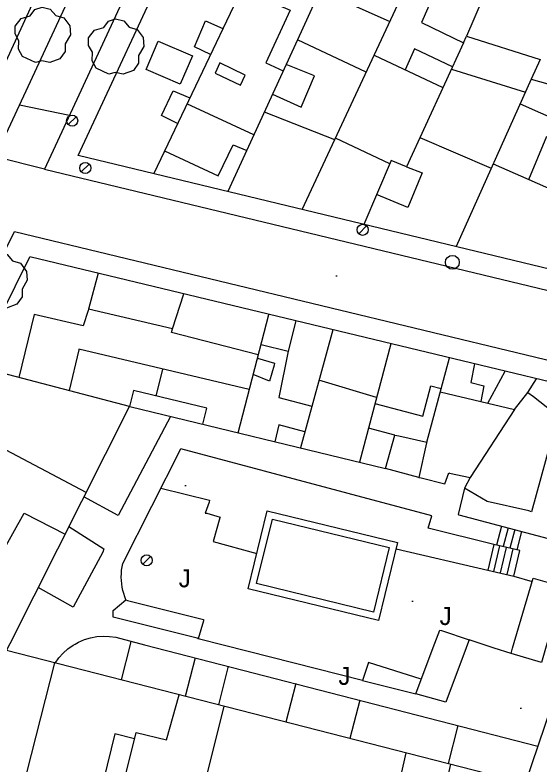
# Model space of a CAD drawing. Extents: x 431390 to 432653, y 4586754 to 4589600.
# Drawn here: x 432007.4 to 432045.3, y 4587636.5 to 4587690.5 of the extents above; entities that cross this region are included whole.
import ezdxf

# ---------------------------------------------------------------- set-up
doc = ezdxf.new("R2010")
doc.units = 0
for name, color, linetype in [('COM_17LS_LN', 7, 'Continuous'), ('COM_51_LN', 7, 'Continuous'), ('CON_01_LN', 7, 'Continuous'), ('CON_01FI_LN', 7, 'Continuous'), ('CON_03_LN', 7, 'Continuous'), ('CON_04_LN', 7, 'Continuous'), ('CON_07_LN', 7, 'Continuous'), ('CON_14LS_LN', 7, 'Continuous'), ('CON_15_LN', 7, 'Continuous'), ('CON_16_LN', 7, 'Continuous'), ('CON_23_LN', 7, 'Continuous'), ('CON_29_LN', 7, 'Continuous'), ('ENE_05_PT', 7, 'Continuous'), ('ENE_06_PT', 7, 'Continuous'), ('HID_11EX_LN', 7, 'Continuous'), ('HID_11IN_LN', 7, 'Continuous'), ('ORO_03_PT', 7, 'Continuous'), ('TOP_15JA_TX', 7, 'Continuous'), ('VEG_03_PT', 7, 'Continuous'), ('VEG_06_LN', 7, 'Continuous')]:
    doc.layers.add(name, color=color, linetype=linetype)

msp = doc.modelspace()

# ---------------------------------------------------------------- linework, layer by layer
at = {"layer": 'COM_17LS_LN'}
for points in [[(432006.024, 4587680.292), (432041.411, 4587756.509), (432044.673, 4587755.098), (432041.441, 4587748.129), (432031.405, 4587726.494), (432019.334, 4587700.469), (432009.569, 4587679.418), (432092.063, 4587659.53)], [(431996.705, 4587653.49), (432007.414, 4587674.901), (432066.476, 4587660.674)]]:
    msp.add_lwpolyline(points, dxfattribs=at)
at = {"layer": 'COM_51_LN'}
for points in [[(432007.767, 4587684.047), (432011.367, 4587683.294)], [(432009.569, 4587679.418), (432006.024, 4587680.292)]]:
    msp.add_lwpolyline(points, dxfattribs=at)
at = {"layer": 'CON_01_LN'}
for points in [[(432028.804, 4587732.074), (432027.658, 4587732.613), (432004.401, 4587682.062), (431964.751, 4587691.684)], [(432069.351, 4587666.555), (432012.008, 4587680.398), (432019.086, 4587695.657)], [(432149.679, 4587598.561), (432142.834, 4587600.154), (432120.838, 4587605.458), (432120.688, 4587605.494), (432084.332, 4587614.171), (432084.249, 4587614.151), (432049.937, 4587622.578), (431990.859, 4587637.415), (431994.764, 4587645.305), (432008.507, 4587673.078)], [(432080.515, 4587655.754), (432008.507, 4587673.078)]]:
    msp.add_lwpolyline(points, dxfattribs=at)
at = {"layer": 'CON_01FI_LN'}
for points in [[(432037.686, 4587692.072), (432036.767, 4587689.999), (432039.8, 4587688.515), (432040.023, 4587689.014), (432045.332, 4587687.328), (432044.693, 4587685.898), (432048.742, 4587684.772), (432051.08, 4587689.672), (432055.373, 4587687.519), (432063.231, 4587702.643)], [(432047.563, 4587644.797), (432044.268, 4587635.081), (432006.82, 4587644.663), (432007.084, 4587645.187), (432015.694, 4587662.285), (432015.737, 4587662.272), (432034.19, 4587657.797), (432034.86, 4587660.208), (432035.137, 4587660.172), (432037.16, 4587659.697), (432037.143, 4587659.656), (432036.593, 4587657.168), (432036.755, 4587657.127), (432038.472, 4587656.7), (432038.755, 4587657.502), (432038.809, 4587657.469), (432040.297, 4587657.161), (432039.882, 4587656.377), (432039.414, 4587654.497), (432039.468, 4587654.474), (432049.901, 4587651.69), (432047.563, 4587644.797)]]:
    msp.add_lwpolyline(points, dxfattribs=at)
at = {"layer": 'CON_03_LN'}
for points in [[(432026.951, 4587699.037), (432017.456, 4587679.083)], [(432031.928, 4587697.709), (432027.825, 4587688.744)], [(432028.171, 4587676.496), (432035.4, 4587692.026)], [(432027.825, 4587688.744), (432027.011, 4587686.967)], [(432039.8, 4587688.515), (432035.704, 4587679.584), (432034.583, 4587680.032), (432032.626, 4587675.421)], [(432027.011, 4587686.967), (432022.811, 4587677.79)], [(432044.693, 4587685.898), (432039.278, 4587673.815)], [(432023.536, 4587660.381), (432025.763, 4587668.927)], [(432030.382, 4587667.815), (432028.037, 4587659.289)], [(432034.552, 4587666.812), (432032.308, 4587658.253)], [(432037.16, 4587659.697), (432038.792, 4587665.792)], [(432015.694, 4587662.285), (432004.605, 4587665.192)], [(432044.454, 4587663.281), (432045.084, 4587664.278)], [(432043.499, 4587662.06), (432044.454, 4587663.281)], [(432043.499, 4587662.06), (432040.297, 4587657.161)], [(432010.29, 4587643.775), (432007.611, 4587633.208)]]:
    msp.add_lwpolyline(points, dxfattribs=at)
at = {"layer": 'CON_04_LN'}
for points in [[(432023.785, 4587692.384), (432027.29, 4587690.869), (432025.533, 4587687.079), (432026.794, 4587686.492)], [(432029.462, 4587692.321), (432034.488, 4587690.066)], [(432021.547, 4587687.681), (432020.394, 4587688.229), (432021.179, 4587690.103), (432022.445, 4587689.567)], [(432017.78, 4587688.645), (432020.246, 4587687.592), (432019.372, 4587685.545), (432016.905, 4587686.598), (432017.78, 4587688.645)], [(432032.788, 4587686.414), (432027.825, 4587688.744)], [(432039.009, 4587686.791), (432036.283, 4587688.1), (432035.586, 4587686.578)], [(432033.352, 4587687.626), (432038.323, 4587685.295)], [(432024.063, 4587686.196), (432022.226, 4587687.072), (432021.877, 4587686.341), (432023.714, 4587685.464), (432024.063, 4587686.196)], [(432026.033, 4587684.83), (432028.093, 4587683.874), (432029.057, 4587686.15), (432027.011, 4587686.967)], [(432038.932, 4587686.622), (432044.277, 4587684.969)], [(432019.18, 4587682.705), (432018.009, 4587683.271), (432018.864, 4587685.07), (432020.064, 4587684.563)], [(432043.898, 4587684.124), (432048.088, 4587682.264), (432049.392, 4587685.166), (432053.673, 4587684.023)], [(432024.68, 4587681.873), (432019.854, 4587684.123)], [(432044.533, 4587678.666), (432045.829, 4587681.781), (432048.52, 4587680.597), (432047.155, 4587677.517)], [(432018.242, 4587680.734), (432022.116, 4587678.933), (432023.182, 4587681.163), (432024.163, 4587680.745)], [(432035.704, 4587679.584), (432036.819, 4587679.14), (432035.79, 4587676.639), (432033.541, 4587677.578)], [(432044.533, 4587678.666), (432047.155, 4587677.517)], [(432013.441, 4587671.891), (432012.744, 4587669.315)], [(432018.811, 4587667.875), (432019.629, 4587670.402)], [(432025, 4587665.998), (432018.747, 4587667.628), (432018.811, 4587667.875), (432012.744, 4587669.315), (432012.713, 4587669.22), (432012.363, 4587668.104), (432008.833, 4587668.913), (432007.72, 4587664.375)], [(432027.715, 4587668.457), (432027.149, 4587666.272), (432026.489, 4587662.934), (432028.865, 4587662.299)], [(432024.349, 4587663.499), (432012.056, 4587666.427), (432012.057, 4587666.362), (432011.346, 4587663.425)], [(432025.199, 4587666.761), (432027.149, 4587666.272)], [(432024.94, 4587665.767), (432026.162, 4587665.415), (432026.137, 4587665.267), (432025.797, 4587664.103), (432024.631, 4587664.584)], [(432040.594, 4587665.358), (432040.326, 4587664.022), (432041.286, 4587663.772), (432041.059, 4587662.638)], [(432017.621, 4587663.037), (432018.107, 4587664.986)], [(432041.571, 4587662.517), (432042.804, 4587664.827)], [(432033.42, 4587662.494), (432036.876, 4587661.588), (432037.45, 4587663.778), (432038.2, 4587663.581)], [(432021.005, 4587660.994), (432021.285, 4587662.149), (432015.989, 4587663.432), (432015.694, 4587662.285)], [(432038.133, 4587663.331), (432043.499, 4587662.06)], [(432044.454, 4587663.281), (432044.858, 4587662.991), (432046.225, 4587661.91), (432046.324, 4587661.657), (432046.467, 4587661.177), (432046.463, 4587661.068), (432044.713, 4587654.69), (432044.513, 4587654.761), (432041.515, 4587655.419), (432039.882, 4587656.377)], [(432028.355, 4587660.446), (432026.49, 4587660.959), (432026.191, 4587659.737)], [(432034.86, 4587660.208), (432032.951, 4587660.707)], [(432012.571, 4587656.084), (432005.955, 4587659.561), (432002.96, 4587653.376), (432003.125, 4587653.286), (432006.464, 4587651.651), (432008.109, 4587654.589), (432011.052, 4587653.067)], [(432022.51, 4587640.648), (432020.707, 4587633.426), (432015.203, 4587634.799), (432016.192, 4587638.765), (432018.382, 4587638.218), (432019.282, 4587641.474)], [(432016.077, 4587638.303), (432014.655, 4587638.658), (432013.82, 4587635.319), (432015.244, 4587634.963)], [(432038.859, 4587636.465), (432037.219, 4587629.268), (432031.639, 4587630.539), (432032.567, 4587634.615), (432034.94, 4587634.074), (432035.67, 4587637.281)]]:
    msp.add_lwpolyline(points, dxfattribs=at)
at = {"layer": 'CON_07_LN'}
for points in [[(432043.239, 4587644.448), (432043.353, 4587644.838), (432044.833, 4587649.904), (432047.021, 4587649.264), (432045.721, 4587644.815), (432045.427, 4587643.808), (432043.239, 4587644.448)], [(432015.452, 4587648.323), (432015.559, 4587648.284), (432021.052, 4587646.902), (432021.037, 4587646.826), (432020.652, 4587645.525), (432020.583, 4587645.565), (432014.528, 4587647.075), (432014.519, 4587647.181), (432014.516, 4587647.568), (432015.452, 4587648.323)], [(432036.364, 4587641.555), (432037.63, 4587644.893), (432038.104, 4587646.141), (432038.209, 4587646.127), (432040.216, 4587645.444), (432040.175, 4587645.317), (432040.008, 4587644.87), (432038.538, 4587640.935), (432036.364, 4587641.555)], [(432036.764, 4587642.61), (432032.944, 4587643.802), (432032.524, 4587642.511), (432036.364, 4587641.555)]]:
    msp.add_lwpolyline(points, dxfattribs=at)
at = {"layer": 'CON_14LS_LN'}
for points in [[(432041.999, 4587652.33), (432037.267, 4587653.498), (432037.532, 4587654.386), (432019.402, 4587659.236)], [(432043.447, 4587650.039), (432044.76, 4587649.655)]]:
    msp.add_lwpolyline(points, dxfattribs=at)
at = {"layer": 'CON_15_LN'}
msp.add_lwpolyline([(432041.76, 4587693.043), (432040.023, 4587689.014)], dxfattribs=at)
at = {"layer": 'CON_16_LN'}
for points in [[(432018.655, 4587661.564), (432014.9, 4587654.419), (432012.408, 4587655.759)], [(432015.452, 4587648.323), (432015.364, 4587648.549), (432015.289, 4587648.78), (432015.227, 4587649.014), (432015.178, 4587649.252), (432015.143, 4587649.492), (432015.121, 4587649.734), (432015.113, 4587649.977), (432015.118, 4587650.219), (432015.136, 4587650.461), (432015.168, 4587650.702), (432015.214, 4587650.941), (432019.402, 4587659.236)], [(432036.593, 4587657.168), (432034.19, 4587657.797)], [(432011.331, 4587653.622), (432013.855, 4587652.002), (432013.772, 4587651.777), (432011.635, 4587647.789), (432009.114, 4587649.219)], [(432010.348, 4587643.76), (432010.614, 4587644.133), (432010.92, 4587644.476), (432011.261, 4587644.783), (432011.634, 4587645.05), (432011.796, 4587645.141), (432012.034, 4587645.276), (432012.456, 4587645.456), (432012.895, 4587645.59), (432013.347, 4587645.674), (432013.804, 4587645.709), (432014.263, 4587645.694), (432014.718, 4587645.629), (432016.796, 4587645.093), (432045.182, 4587637.775)], [(432015.814, 4587645.346), (432015.752, 4587645.103), (432015.097, 4587642.545)], [(432032.524, 4587642.511), (432022.571, 4587645.038), (432020.652, 4587645.525)], [(432020.449, 4587644.151), (432019.734, 4587641.359)], [(432022.837, 4587643.536), (432022.123, 4587640.747)], [(432027.697, 4587642.283), (432026.985, 4587639.503)], [(432032.324, 4587641.09), (432031.615, 4587638.319)], [(432039.398, 4587639.266), (432038.692, 4587636.508)]]:
    msp.add_lwpolyline(points, dxfattribs=at)
at = {"layer": 'CON_23_LN'}
for points in [[(432042.554, 4587653.65), (432042.19, 4587652.285)], [(432043.036, 4587653.522), (432042.676, 4587652.171)], [(432043.518, 4587653.393), (432043.162, 4587652.057)], [(432044, 4587653.265), (432043.648, 4587651.943)], [(432041.999, 4587652.33), (432041.565, 4587650.481)], [(432041.989, 4587650.381), (432042.423, 4587652.23)], [(432043.447, 4587650.039), (432043.881, 4587651.888), (432041.999, 4587652.33)], [(432042.475, 4587650.267), (432042.909, 4587652.116)], [(432042.961, 4587650.153), (432043.395, 4587652.002)], [(432041.565, 4587650.481), (432043.447, 4587650.039)]]:
    msp.add_lwpolyline(points, dxfattribs=at)
at = {"layer": 'CON_29_LN'}
for points in [[(432030.515, 4587681.532), (432025.436, 4587683.526)], [(432034.486, 4587679.803), (432030.565, 4587681.639)], [(432036.668, 4587681.687), (432041.814, 4587679.475)], [(432041.958, 4587679.795), (432044.533, 4587678.666)], [(432033.534, 4587662.93), (432029.379, 4587664.169)]]:
    msp.add_lwpolyline(points, dxfattribs=at)
at = {"layer": 'ENE_05_PT'}
msp.add_circle((432039.004, 4587672.685), 0.5, dxfattribs=at)
at = {"layer": 'ENE_06_PT'}
for p, q in [((432011.853, 4587683.189), (432011.287, 4587682.623)), ((432012.795, 4587679.771), (432012.229, 4587679.205)), ((432032.814, 4587675.314), (432032.248, 4587674.748)), ((432017.223, 4587651.462), (432016.657, 4587650.896))]:
    msp.add_line(p, q, dxfattribs=at)
for centre in [(432011.57, 4587682.906), (432012.512, 4587679.488), (432032.531, 4587675.031), (432016.94, 4587651.179)]:
    msp.add_circle(centre, 0.4, dxfattribs=at)
at = {"layer": 'HID_11EX_LN'}
msp.add_lwpolyline([(432025.649, 4587654.759), (432035.046, 4587652.463), (432033.672, 4587646.84), (432024.275, 4587649.135), (432025.649, 4587654.759)], dxfattribs=at)
at = {"layer": 'HID_11IN_LN'}
msp.add_lwpolyline([(432026.016, 4587654.156), (432034.443, 4587652.097), (432033.306, 4587647.444), (432024.879, 4587649.502), (432026.016, 4587654.156)], dxfattribs=at)
at = {"layer": 'ORO_03_PT'}
for p, q in [((432030.598, 4587671.706), (432030.698, 4587671.706)), ((432019.695, 4587656.588), (432019.795, 4587656.588)), ((432036.069, 4587648.225), (432036.169, 4587648.225)), ((432043.886, 4587640.516), (432043.986, 4587640.516))]:
    msp.add_line(p, q, dxfattribs=at)
at = {"layer": 'VEG_03_PT'}
for points in [[(432008.918, 4587687.108), (432007.991, 4587687.543), (432007.703, 4587688.064), (432007.726, 4587688.678), (432007.444, 4587689.17), (432007.452, 4587689.733), (432007.893, 4587690.268), (432008.546, 4587690.472), (432008.881, 4587690.923), (432009.407, 4587691.093), (432009.987, 4587690.96), (432010.387, 4587690.494), (432010.961, 4587690.324), (432011.395, 4587689.741), (432011.444, 4587689.099), (432011.061, 4587688.452), (432011.061, 4587687.902), (432010.689, 4587687.368), (432009.95, 4587687.093), (432009.385, 4587687.221), (432008.918, 4587687.108)], [(432014.216, 4587686.27), (432013.289, 4587686.705), (432013.001, 4587687.226), (432013.024, 4587687.84), (432012.742, 4587688.332), (432012.75, 4587688.895), (432013.191, 4587689.43), (432013.844, 4587689.634), (432014.179, 4587690.085), (432014.705, 4587690.255), (432015.285, 4587690.122), (432015.685, 4587689.656), (432016.259, 4587689.486), (432016.693, 4587688.903), (432016.742, 4587688.261), (432016.359, 4587687.614), (432016.359, 4587687.064), (432015.987, 4587686.53), (432015.248, 4587686.255), (432014.683, 4587686.383), (432014.216, 4587686.27)], [(432005.806, 4587669.4), (432004.879, 4587669.835), (432004.591, 4587670.356), (432004.614, 4587670.97), (432004.332, 4587671.462), (432004.34, 4587672.025), (432004.781, 4587672.56), (432005.434, 4587672.764), (432005.769, 4587673.215), (432006.295, 4587673.385), (432006.875, 4587673.252), (432007.275, 4587672.786), (432007.849, 4587672.616), (432008.283, 4587672.033), (432008.332, 4587671.391), (432007.949, 4587670.744), (432007.949, 4587670.194), (432007.577, 4587669.66), (432006.838, 4587669.385), (432006.273, 4587669.513), (432005.806, 4587669.4)]]:
    msp.add_lwpolyline(points, dxfattribs=at)
at = {"layer": 'VEG_06_LN'}
for points in [[(432017.966, 4587656.391), (432021.468, 4587655.521), (432021.444, 4587655.371), (432021.168, 4587654.595), (432021.291, 4587654.584), (432022.25, 4587654.292), (432022.232, 4587654.251), (432021.732, 4587652.533), (432024.893, 4587651.664)], [(432034.937, 4587652.016), (432041.565, 4587650.481)], [(432043.239, 4587644.448), (432042.017, 4587644.851), (432040.216, 4587645.444)]]:
    msp.add_lwpolyline(points, dxfattribs=at)

# ---------------------------------------------------------------- texts
at = {"layer": 'TOP_15JA_TX'}
for p in [(432019.257, 4587649.235), (432038.082, 4587646.512), (432030.783, 4587642.193)]:
    msp.add_text('J', height=1.3, dxfattribs=at).set_placement(p)

doc.saveas('drawing.dxf')
